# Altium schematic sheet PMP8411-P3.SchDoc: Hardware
size 431 x 279 mm; Date: Not shown in title block; ApprovedBy: Not shown in title block; CheckedBy: Not shown in title block; Author: Not shown in title block; CompanyName: Not shown in title block; Engineer: Not shown in title block; Organization: Not shown in title block; Address1: Not shown in title block; Address2: Not shown in title block; Address3: Not shown in title block; Address4: Not shown in title block; DocumentNumber: 1; Revision: Use project parameter SCH_Rev; SheetNumber: 3; SheetTotal: 3; PageSetup: Record=PageOptions¦CenterHorizontal=True¦CenterVertical=True¦PrintScale=0.64¦XCorrection=1.00¦YCorrection=1.00¦PrintKind=0¦BorderSize=5000000¦LeftOffset=0¦BottomOffset=0¦Orientation=2¦PaperLength=1000¦PaperWidth=1000¦Scale=100¦PaperSource=15¦PrintQuality=600¦MediaType=1¦DitherType=10¦PrintScaleMode=1¦PaperKind=Letter
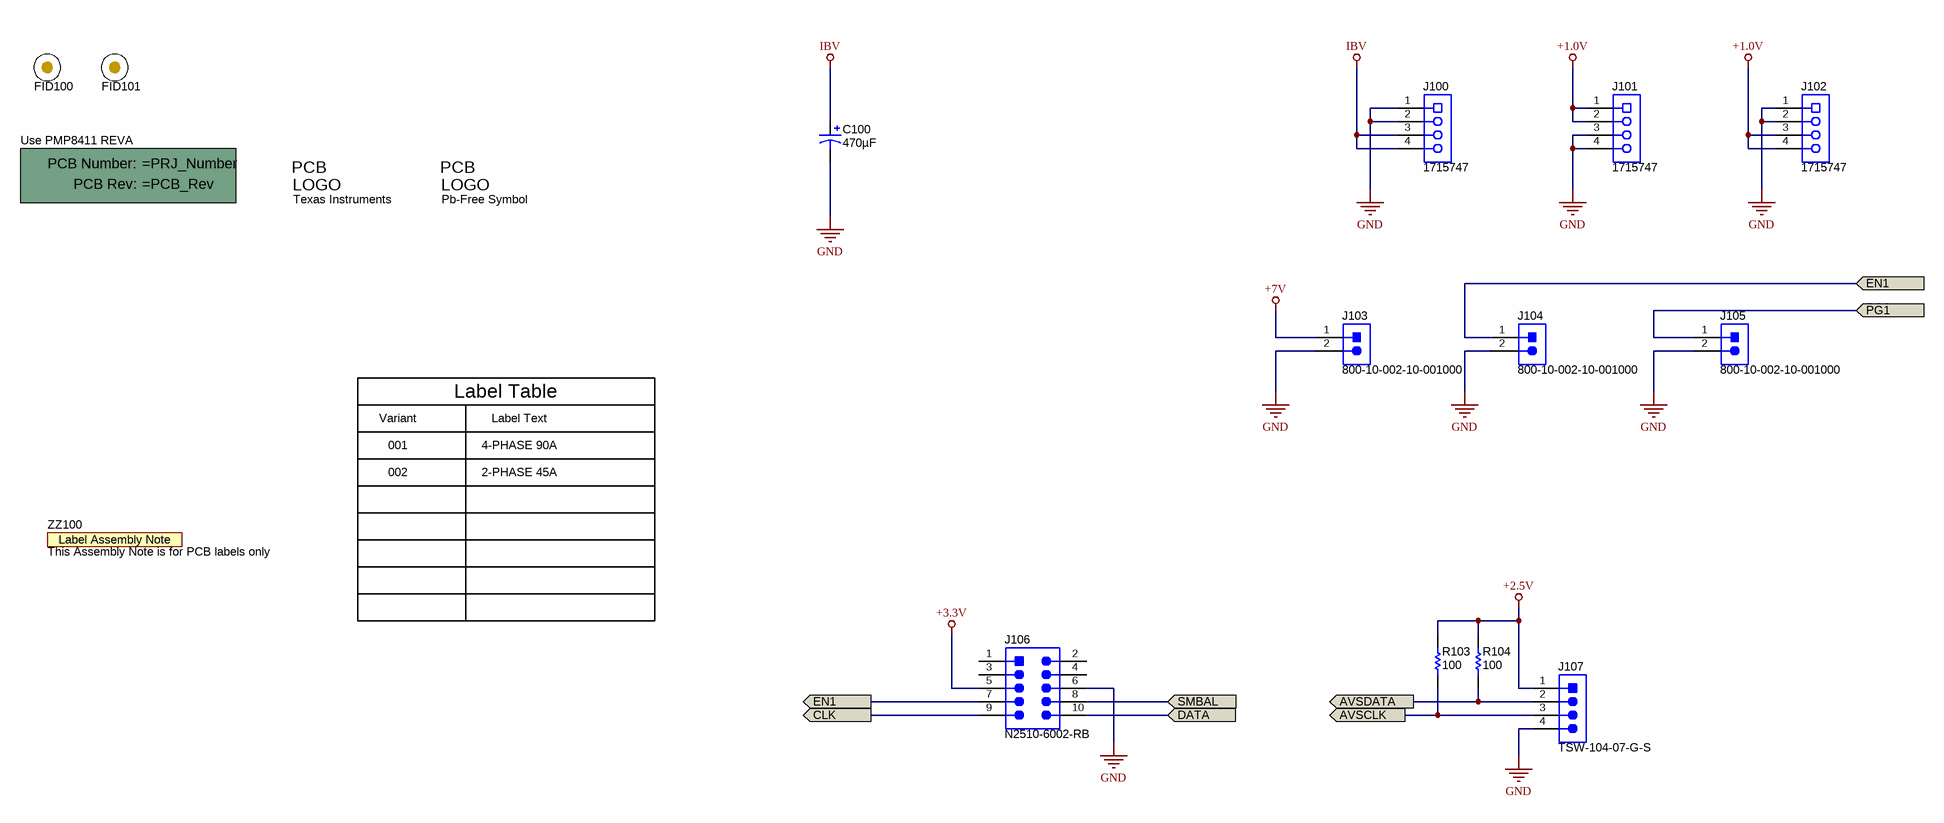
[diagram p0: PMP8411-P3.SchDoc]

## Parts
!PCB100  Use PMP8411 REVA  (mechanical)
C100  ValueDisplayed: 470µF  [CAPSMT_62_JC0]  (hidden comment: 16SVPE470M)
FID100  Fiducial  [Fiducial10-20]  (value not drawn)
FID101  Fiducial  [Fiducial10-20]  (value not drawn)
J100  1715747  [Phoenix_1715747]
J101  1715747  [Phoenix_1715747]
J102  1715747  [Phoenix_1715747]
J103  800-10-002-10-001000  [Mill-Max_800-10-002-10-001000]
J104  800-10-002-10-001000  [Mill-Max_800-10-002-10-001000]
J105  800-10-002-10-001000  [Mill-Max_800-10-002-10-001000]
J106  N2510-6002-RB  [CONN_2510-6002]
J107  TSW-104-07-G-S  [TSW-104-07-G-S]
Logo100  Texas Instruments  [TI_Stacked_Overlay_Small]  (no BOM)
Logo101  Pb-Free Symbol  [Pb-Free_Overlay_Small]  (no BOM)
R103  ValueDisplayed: 100  [0402]  (hidden comment: RG1005P-101-B-T5)
R104  ValueDisplayed: 100  [0402]  (hidden comment: RG1005P-101-B-T5)
ZZ100  This Assembly Note is for PCB labels only  [AssemblyNoteLabel]  (no BOM)

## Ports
AVSCLK, AVSDATA, CLK, DATA, EN1, PG1, SMBAL

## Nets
+1.0V: J101.1 J101.2 J102.3 J102.4
+2.5V: J107.1 R103.2 R104.2
+3.3V: J106.5
+7V: J103.1
GND: C100.2(-) J100.1 J100.2 J101.3 J101.4 J102.1 J102.2 J103.2 J104.2 J105.2 J106.6 J107.4
IBV: C100.1(+) J100.3 J100.4
AVSCLK: J107.3 R103.1 ; port AVSCLK
AVSDATA: J107.2 R104.1 ; port AVSDATA
CLK: J106.9 ; port CLK
DATA: J106.10 ; port DATA
EN1: J104.1 J106.7 ; port EN1
PG1: J105.1 ; port PG1
SMBAL: J106.8 ; port SMBAL

Not connected (* = marked no-connect by the designer): J106 1 2 3 4

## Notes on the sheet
- Variant
- Label Table
- Label Text
- 001
- 002
- 4-PHASE 90A
- 2-PHASE 45A

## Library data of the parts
!PCB100 = PCB: Printed Circuit Board; Manufacturer: Any; SymbolCreator: a0412235
C100 = 16SVPE470M: CAP, AL, 470 µF, 16 V, +/- 20%, 0.01 ohm, SMD; Manufacturer: Panasonic; Polarized: Y; CompType: Capacitor; Value: 470uF; U/M: EA; Cap_F: 0.00047; Tolerance_%: 20; VDC_V: 16; Value2: 16V; ESR_ohm: 0.01; IRMS_A: 6.1; TaMin_C: -55; TaMax_C: 105
FID100 FID101 = Fiducial: Fiducial mark.  There is nothing to buy or mount.; SymbolCreator: codlsc
J100-J102 = 1715747: Terminal Block, 5.08mm, 4x1, TH; Manufacturer: Phoenix Contact; SymbolCreator: a0411947; U/M: EA
J103-J105 = 800-10-002-10-001000: Header, 100mil, 2x1, TH; Manufacturer: Mill-Max; SymbolCreator: a0412235; U/M: EA
J106 = N2510-6002-RB: Header (shrouded), 100mil, 5x2, High-Temperature, Gold, TH; Manufacturer: 3M; SymbolCreator: a0412235; U/M: EA
J107 = TSW-104-07-G-S: Header, 100mil, 4x1, Gold, TH; Manufacturer: Samtec; SymbolCreator: a0412235; U/M: EA
Logo100 = TI_Logo: Texas Instrument Corporate Signature; SymbolCreator: codlsc
Logo101 = Pb-Free: SymbolCreator: a0412235
R103 R104 = RG1005P-101-B-T5: RES, 100, 0.1%, 0.063 W, 0402; Manufacturer: Susumu Co Ltd; CompType: Resistor; Value: 100; Value_Code: 100R; Tolerance_%: 0.1; Power_W: 0.063; Value2: 0.063W; TempCo: 25 ppm/C; EIA_Code: E192; U/M: EA
ZZ100 = AssemblyNoteLabel: SymbolCreator: a0412235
